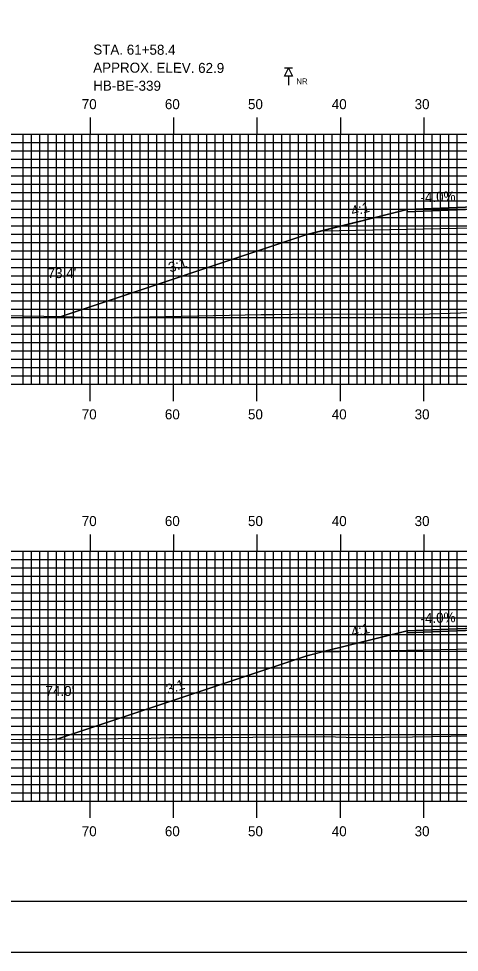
# Model space of a CAD drawing. Extents: x 1757856 to 1758199, y 442591 to 442811.
# Drawn here: x 1757943.1 to 1757995.9, y 442590.5 to 442702.5 of the extents above; entities that cross this region are included whole.
import ezdxf

# ---------------------------------------------------------------- set-up
doc = ezdxf.new("R2010")
doc.units = 0
for name, color, linetype in [('ANNOTATION', 7, 'Continuous'), ('BORDER', 7, 'Continuous'), ('BORING - NO REFUSAL', 7, 'Continuous'), ('D_Roadway_Centerline', 7, 'Continuous'), ('D_Roadway_Edge_Shoulder', 7, 'Continuous'), ('D_Roadway_SlopeLines', 7, 'Continuous'), ('D_Roadway_SubGrade', 7, 'Continuous'), ('D_Text_Standard', 7, 'Continuous'), ('H_V ANNOTATION', 7, 'Continuous'), ('MAJOR', 7, 'Continuous'), ('MINOR', 7, 'Continuous'), ('PLOT BOUNDARY', 7, 'Continuous'), ('S_Roadway_Centerline', 7, 'Continuous')]:
    doc.layers.add(name, color=color, linetype=linetype)

msp = doc.modelspace()

# ---------------------------------------------------------------- linework, layer by layer
at = {"layer": 'BORDER'}
msp.add_lwpolyline([(1757872.02, 442596.67), (1758192.02, 442596.67), (1758192.02, 442806.67), (1757872.02, 442806.67)], close=True, dxfattribs=at)
at = {"layer": 'BORING - NO REFUSAL'}
for p, q in [((1757975.9, 442696.57), (1757974.94, 442696.57)), ((1757975.42, 442695.61), (1757975.42, 442694.55))]:
    msp.add_line(p, q, dxfattribs=at)
msp.add_lwpolyline([(1757975.42, 442696.57), (1757975.9, 442695.61), (1757974.94, 442695.61)], close=True, dxfattribs=at)
at = {"layer": 'D_Roadway_Centerline'}
for points in [[(1757948.18, 442666.8), (1757977.62, 442676.62), (1757979.45, 442677.07), (1757989.62, 442679.62), (1757997.62, 442679.94), (1758009.62, 442680.18), (1758021.62, 442680.42), (1758033.62, 442680.18), (1758041.62, 442679.86), (1758051.8, 442677.31), (1758053.62, 442676.86), (1758074.42, 442669.92)], [(1757947.64, 442616.12), (1757977.62, 442626.12), (1757979.45, 442626.57), (1757989.62, 442629.12), (1757997.62, 442629.44), (1758009.62, 442629.68), (1758021.62, 442629.92), (1758033.62, 442629.68), (1758041.62, 442629.36), (1758051.8, 442626.81), (1758053.62, 442626.36), (1758079.65, 442617.68)]]:
    msp.add_lwpolyline(points, dxfattribs=at)
at = {"layer": 'D_Roadway_Edge_Shoulder'}
for points in [[(1757997.62, 442679.94), (1757989.62, 442679.62), (1757989.62, 442679.37), (1757997.62, 442679.69)], [(1757997.62, 442629.44), (1757989.62, 442629.12), (1757989.62, 442628.87), (1757997.62, 442629.19)]]:
    msp.add_lwpolyline(points, close=True, dxfattribs=at)
at = {"layer": 'D_Roadway_SlopeLines'}
for points in [[(1757989.62, 442679.62), (1757977.62, 442676.62), (1757948.18, 442666.8)], [(1757989.62, 442629.12), (1757977.62, 442626.12), (1757947.64, 442616.12)]]:
    msp.add_lwpolyline(points, dxfattribs=at)
at = {"layer": 'D_Roadway_SubGrade'}
for points in [[(1757997.62, 442679.27), (1757997.62, 442679.69), (1757989.62, 442679.37), (1757989.62, 442679.62), (1757979.45, 442677.07), (1757997.62, 442677.44)], [(1757997.62, 442628.77), (1757997.62, 442629.19), (1757989.62, 442628.87), (1757989.62, 442629.12), (1757979.45, 442626.57), (1757997.62, 442626.94)]]:
    msp.add_lwpolyline(points, close=True, dxfattribs=at)
at = {"layer": 'MAJOR'}
for p, q in [((1757951.62, 442690.67), (1757951.62, 442688.67)), ((1757961.62, 442690.67), (1757961.62, 442688.67)), ((1757971.62, 442690.67), (1757971.62, 442688.67)), ((1757981.62, 442690.67), (1757981.62, 442688.67)), ((1757991.62, 442690.67), (1757991.62, 442688.67)), ((1757881.62, 442688.67), (1758161.62, 442688.67)), ((1757881.62, 442688.67), (1758161.62, 442688.67)), ((1757951.62, 442658.67), (1757951.62, 442688.67)), ((1757961.62, 442658.67), (1757961.62, 442688.67)), ((1757971.62, 442658.67), (1757971.62, 442688.67)), ((1757981.62, 442658.67), (1757981.62, 442688.67)), ((1757991.62, 442658.67), (1757991.62, 442688.67)), ((1757881.62, 442683.67), (1758161.62, 442683.67)), ((1757881.62, 442678.67), (1758161.62, 442678.67)), ((1757881.62, 442673.67), (1758161.62, 442673.67)), ((1757881.62, 442668.67), (1758161.62, 442668.67)), ((1757881.62, 442663.67), (1758161.62, 442663.67)), ((1757881.62, 442658.67), (1758161.62, 442658.67)), ((1757881.62, 442658.67), (1758161.62, 442658.67)), ((1757951.62, 442656.66), (1757951.62, 442658.67)), ((1757961.62, 442656.66), (1757961.62, 442658.67)), ((1757971.62, 442656.66), (1757971.62, 442658.67)), ((1757981.62, 442656.66), (1757981.62, 442658.67)), ((1757991.62, 442656.66), (1757991.62, 442658.67)), ((1757951.62, 442640.67), (1757951.62, 442638.67)), ((1757961.62, 442640.67), (1757961.62, 442638.67)), ((1757971.62, 442640.67), (1757971.62, 442638.67)), ((1757981.62, 442640.67), (1757981.62, 442638.67)), ((1757991.62, 442640.67), (1757991.62, 442638.67)), ((1757881.62, 442638.67), (1758161.62, 442638.67)), ((1757881.62, 442638.67), (1758161.62, 442638.67)), ((1757951.62, 442608.67), (1757951.62, 442638.67)), ((1757961.62, 442608.67), (1757961.62, 442638.67)), ((1757971.62, 442608.67), (1757971.62, 442638.67)), ((1757981.62, 442608.67), (1757981.62, 442638.67)), ((1757991.62, 442608.67), (1757991.62, 442638.67)), ((1757881.62, 442633.67), (1758161.62, 442633.67)), ((1757881.62, 442628.67), (1758161.62, 442628.67)), ((1757881.62, 442623.67), (1758161.62, 442623.67)), ((1757881.62, 442618.67), (1758161.62, 442618.67)), ((1757881.62, 442613.67), (1758161.62, 442613.67)), ((1757881.62, 442608.67), (1758161.62, 442608.67)), ((1757881.62, 442608.67), (1758161.62, 442608.67)), ((1757951.62, 442606.66), (1757951.62, 442608.67)), ((1757961.62, 442606.66), (1757961.62, 442608.67)), ((1757971.62, 442606.66), (1757971.62, 442608.67)), ((1757981.62, 442606.66), (1757981.62, 442608.67)), ((1757991.62, 442606.66), (1757991.62, 442608.67))]:
    msp.add_line(p, q, dxfattribs=at)
at = {"layer": 'MINOR'}
for p, q in [((1757943.62, 442658.67), (1757943.62, 442688.67)), ((1757944.62, 442658.67), (1757944.62, 442688.67)), ((1757945.62, 442658.67), (1757945.62, 442688.67)), ((1757946.62, 442658.67), (1757946.62, 442688.67)), ((1757947.62, 442658.67), (1757947.62, 442688.67)), ((1757948.62, 442658.67), (1757948.62, 442688.67)), ((1757949.62, 442658.67), (1757949.62, 442688.67)), ((1757950.62, 442658.67), (1757950.62, 442688.67)), ((1757952.62, 442658.67), (1757952.62, 442688.67)), ((1757953.62, 442658.67), (1757953.62, 442688.67)), ((1757954.62, 442658.67), (1757954.62, 442688.67)), ((1757955.62, 442658.67), (1757955.62, 442688.67)), ((1757956.62, 442658.67), (1757956.62, 442688.67)), ((1757957.62, 442658.67), (1757957.62, 442688.67)), ((1757958.62, 442658.67), (1757958.62, 442688.67)), ((1757959.62, 442658.67), (1757959.62, 442688.67)), ((1757960.62, 442658.67), (1757960.62, 442688.67)), ((1757962.62, 442658.67), (1757962.62, 442688.67)), ((1757963.62, 442658.67), (1757963.62, 442688.67)), ((1757964.62, 442658.67), (1757964.62, 442688.67)), ((1757965.62, 442658.67), (1757965.62, 442688.67)), ((1757966.62, 442658.67), (1757966.62, 442688.67)), ((1757967.62, 442658.67), (1757967.62, 442688.67)), ((1757968.62, 442658.67), (1757968.62, 442688.67)), ((1757969.62, 442658.67), (1757969.62, 442688.67)), ((1757970.62, 442658.67), (1757970.62, 442688.67)), ((1757972.62, 442658.67), (1757972.62, 442688.67)), ((1757973.62, 442658.67), (1757973.62, 442688.67)), ((1757974.62, 442658.67), (1757974.62, 442688.67)), ((1757975.62, 442658.67), (1757975.62, 442688.67)), ((1757976.62, 442658.67), (1757976.62, 442688.67)), ((1757977.62, 442658.67), (1757977.62, 442688.67)), ((1757978.62, 442658.67), (1757978.62, 442688.67)), ((1757979.62, 442658.67), (1757979.62, 442688.67)), ((1757980.62, 442658.67), (1757980.62, 442688.67)), ((1757982.62, 442658.67), (1757982.62, 442688.67)), ((1757983.62, 442658.67), (1757983.62, 442688.67)), ((1757984.62, 442658.67), (1757984.62, 442688.67)), ((1757985.62, 442658.67), (1757985.62, 442688.67)), ((1757986.62, 442658.67), (1757986.62, 442688.67)), ((1757987.62, 442658.67), (1757987.62, 442688.67)), ((1757988.62, 442658.67), (1757988.62, 442688.67)), ((1757989.62, 442658.67), (1757989.62, 442688.67)), ((1757990.62, 442658.67), (1757990.62, 442688.67)), ((1757992.62, 442658.67), (1757992.62, 442688.67)), ((1757993.62, 442658.67), (1757993.62, 442688.67)), ((1757994.62, 442658.67), (1757994.62, 442688.67)), ((1757995.62, 442658.67), (1757995.62, 442688.67)), ((1757881.62, 442687.67), (1758161.62, 442687.67)), ((1757881.62, 442686.67), (1758161.62, 442686.67)), ((1757881.62, 442685.67), (1758161.62, 442685.67)), ((1757881.62, 442684.67), (1758161.62, 442684.67)), ((1757881.62, 442682.67), (1758161.62, 442682.67)), ((1757881.62, 442681.67), (1758161.62, 442681.67)), ((1757881.62, 442680.67), (1758161.62, 442680.67)), ((1757881.62, 442679.67), (1758161.62, 442679.67)), ((1757881.62, 442677.67), (1758161.62, 442677.67)), ((1757881.62, 442676.67), (1758161.62, 442676.67)), ((1757881.62, 442675.67), (1758161.62, 442675.67)), ((1757881.62, 442674.67), (1758161.62, 442674.67)), ((1757881.62, 442672.67), (1758161.62, 442672.67)), ((1757881.62, 442671.67), (1758161.62, 442671.67)), ((1757881.62, 442670.67), (1758161.62, 442670.67)), ((1757881.62, 442669.67), (1758161.62, 442669.67)), ((1757881.62, 442667.67), (1758161.62, 442667.67)), ((1757881.62, 442666.67), (1758161.62, 442666.67)), ((1757881.62, 442665.67), (1758161.62, 442665.67)), ((1757881.62, 442664.67), (1758161.62, 442664.67)), ((1757881.62, 442662.67), (1758161.62, 442662.67)), ((1757881.62, 442661.67), (1758161.62, 442661.67)), ((1757881.62, 442660.67), (1758161.62, 442660.67)), ((1757881.62, 442659.67), (1758161.62, 442659.67)), ((1757943.62, 442608.67), (1757943.62, 442638.67)), ((1757944.62, 442608.67), (1757944.62, 442638.67)), ((1757945.62, 442608.67), (1757945.62, 442638.67)), ((1757946.62, 442608.67), (1757946.62, 442638.67)), ((1757947.62, 442608.67), (1757947.62, 442638.67)), ((1757948.62, 442608.67), (1757948.62, 442638.67)), ((1757949.62, 442608.67), (1757949.62, 442638.67)), ((1757950.62, 442608.67), (1757950.62, 442638.67)), ((1757952.62, 442608.67), (1757952.62, 442638.67)), ((1757953.62, 442608.67), (1757953.62, 442638.67)), ((1757954.62, 442608.67), (1757954.62, 442638.67)), ((1757955.62, 442608.67), (1757955.62, 442638.67)), ((1757956.62, 442608.67), (1757956.62, 442638.67)), ((1757957.62, 442608.67), (1757957.62, 442638.67)), ((1757958.62, 442608.67), (1757958.62, 442638.67)), ((1757959.62, 442608.67), (1757959.62, 442638.67)), ((1757960.62, 442608.67), (1757960.62, 442638.67)), ((1757962.62, 442608.67), (1757962.62, 442638.67)), ((1757963.62, 442608.67), (1757963.62, 442638.67)), ((1757964.62, 442608.67), (1757964.62, 442638.67)), ((1757965.62, 442608.67), (1757965.62, 442638.67)), ((1757966.62, 442608.67), (1757966.62, 442638.67)), ((1757967.62, 442608.67), (1757967.62, 442638.67)), ((1757968.62, 442608.67), (1757968.62, 442638.67)), ((1757969.62, 442608.67), (1757969.62, 442638.67)), ((1757970.62, 442608.67), (1757970.62, 442638.67)), ((1757972.62, 442608.67), (1757972.62, 442638.67)), ((1757973.62, 442608.67), (1757973.62, 442638.67)), ((1757974.62, 442608.67), (1757974.62, 442638.67)), ((1757975.62, 442608.67), (1757975.62, 442638.67)), ((1757976.62, 442608.67), (1757976.62, 442638.67)), ((1757977.62, 442608.67), (1757977.62, 442638.67)), ((1757978.62, 442608.67), (1757978.62, 442638.67)), ((1757979.62, 442608.67), (1757979.62, 442638.67)), ((1757980.62, 442608.67), (1757980.62, 442638.67)), ((1757982.62, 442608.67), (1757982.62, 442638.67)), ((1757983.62, 442608.67), (1757983.62, 442638.67)), ((1757984.62, 442608.67), (1757984.62, 442638.67)), ((1757985.62, 442608.67), (1757985.62, 442638.67)), ((1757986.62, 442608.67), (1757986.62, 442638.67)), ((1757987.62, 442608.67), (1757987.62, 442638.67)), ((1757988.62, 442608.67), (1757988.62, 442638.67)), ((1757989.62, 442608.67), (1757989.62, 442638.67)), ((1757990.62, 442608.67), (1757990.62, 442638.67)), ((1757992.62, 442608.67), (1757992.62, 442638.67)), ((1757993.62, 442608.67), (1757993.62, 442638.67)), ((1757994.62, 442608.67), (1757994.62, 442638.67)), ((1757995.62, 442608.67), (1757995.62, 442638.67)), ((1757881.62, 442637.67), (1758161.62, 442637.67)), ((1757881.62, 442636.67), (1758161.62, 442636.67)), ((1757881.62, 442635.67), (1758161.62, 442635.67)), ((1757881.62, 442634.67), (1758161.62, 442634.67)), ((1757881.62, 442632.67), (1758161.62, 442632.67)), ((1757881.62, 442631.67), (1758161.62, 442631.67)), ((1757881.62, 442630.67), (1758161.62, 442630.67)), ((1757881.62, 442629.67), (1758161.62, 442629.67)), ((1757881.62, 442627.67), (1758161.62, 442627.67)), ((1757881.62, 442626.67), (1758161.62, 442626.67)), ((1757881.62, 442625.67), (1758161.62, 442625.67)), ((1757881.62, 442624.67), (1758161.62, 442624.67)), ((1757881.62, 442622.67), (1758161.62, 442622.67)), ((1757881.62, 442621.67), (1758161.62, 442621.67)), ((1757881.62, 442620.67), (1758161.62, 442620.67)), ((1757881.62, 442619.67), (1758161.62, 442619.67)), ((1757881.62, 442617.67), (1758161.62, 442617.67)), ((1757881.62, 442616.67), (1758161.62, 442616.67)), ((1757881.62, 442615.67), (1758161.62, 442615.67)), ((1757881.62, 442614.67), (1758161.62, 442614.67)), ((1757881.62, 442612.67), (1758161.62, 442612.67)), ((1757881.62, 442611.67), (1758161.62, 442611.67)), ((1757881.62, 442610.67), (1758161.62, 442610.67)), ((1757881.62, 442609.67), (1758161.62, 442609.67))]:
    msp.add_line(p, q, dxfattribs=at)
at = {"layer": 'PLOT BOUNDARY'}
msp.add_lwpolyline([(1757855.84, 442590.55), (1758195.84, 442590.55), (1758195.84, 442810.55), (1757855.84, 442810.55)], close=True, dxfattribs=at)
at = {"layer": 'S_Roadway_Centerline'}
for points in [[(1757940.97, 442666.92), (1757948.63, 442666.8), (1757953.07, 442666.66), (1757972.12, 442667.03), (1757973.67, 442667.06), (1757975.85, 442667.09), (1757992.29, 442667.13), (1758003.42, 442667.5), (1758010.86, 442667.58), (1758022.25, 442667.62), (1758030.55, 442667.62), (1758032.62, 442667.64), (1758035.59, 442667.85), (1758050.54, 442668.3), (1758056.8, 442668.11), (1758068.44, 442668.92), (1758068.49, 442668.93), (1758068.52, 442668.92), (1758080.06, 442668.24), (1758097.4, 442668.75)], [(1757937.27, 442616.26), (1757943.12, 442616.08), (1757958.96, 442616.24), (1757961.11, 442616.31), (1757962.39, 442616.31), (1757966.83, 442616.3), (1757979.76, 442616.42), (1757983.6, 442616.32), (1757990.28, 442616.41), (1757997.13, 442616.51), (1758000.42, 442616.54), (1758019.36, 442617.04), (1758020.16, 442617.05), (1758020.4, 442617.06), (1758038, 442616.9), (1758051.77, 442617.14), (1758057.42, 442617.26), (1758067.77, 442617.47), (1758077.01, 442617.74), (1758084.81, 442617.57)]]:
    msp.add_lwpolyline(points, dxfattribs=at)

# ---------------------------------------------------------------- texts
at = {"layer": 'ANNOTATION'}
for s, rotation, p in [('-4.0%', 2.2906, (1757991.25, 442680.48)), ('4:1', 14.0362, (1757983.07, 442678.84)), ('3:1', 18.4348, (1757961.24, 442672.06)), ('-4.0%', 2.2906, (1757991.25, 442629.98)), ('4:1', 14.0362, (1757983.07, 442628.34)), ('3:1', 18.4348, (1757960.97, 442621.47))]:
    msp.add_text(s, height=1.2, rotation=rotation, dxfattribs=at).set_placement(p)
at = {"layer": 'BORING - NO REFUSAL'}
for s, p in [('STA. 61+58.4', (1757952.01, 442698.22)), ('APPROX. ELEV. 62.9', (1757952, 442696.06)), ('HB-BE-339', (1757952, 442693.9))]:
    msp.add_text(s, height=1.2, rotation=359.8142, dxfattribs=at).set_placement(p)
msp.add_text('NR', height=0.7, dxfattribs=at).set_placement((1757976.35, 442694.65))
at = {"layer": 'D_Text_Standard'}
for s, p in [("73.4'", (1757946.54, 442671.41)), ("74.0'", (1757946.28, 442621.29))]:
    msp.add_text(s, height=1.2, dxfattribs=at).set_placement(p)
at = {"layer": 'H_V ANNOTATION'}
for s, p in [('70', (1757950.63, 442691.67)), ('60', (1757960.59, 442691.67)), ('50', (1757970.55, 442691.67)), ('40', (1757980.59, 442691.67)), ('30', (1757990.52, 442691.67)), ('70', (1757950.63, 442654.47)), ('60', (1757960.59, 442654.47)), ('50', (1757970.55, 442654.47)), ('40', (1757980.59, 442654.47)), ('30', (1757990.52, 442654.47)), ('70', (1757950.63, 442641.67)), ('60', (1757960.59, 442641.67)), ('50', (1757970.55, 442641.67)), ('40', (1757980.59, 442641.67)), ('30', (1757990.52, 442641.67)), ('70', (1757950.63, 442604.47)), ('60', (1757960.59, 442604.47)), ('50', (1757970.55, 442604.47)), ('40', (1757980.59, 442604.47)), ('30', (1757990.52, 442604.47))]:
    msp.add_text(s, height=1.2, dxfattribs=at).set_placement(p)

doc.saveas('drawing.dxf')
